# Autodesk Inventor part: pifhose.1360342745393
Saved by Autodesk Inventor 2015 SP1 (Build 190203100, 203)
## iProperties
IsCustomPart: 1
Company: Parker Hannifin
Created: 2013-02
Material: Rubber
Description: Tömlő
Document SubType Name: Modeling
Standard: Parker
Designer: Marci
Manufacturer: Parker
Language: hu-HU
Size Designation: 1/4 - 5
Categories: <MemberInstance><Categories><Category DisplayName="Csővezetékek" InternalName="4347fa0f-2144-441d-94cd-e3e15c92b736" Mnemonic="TUBEANDPIPE"><CategoryParameter D
Stock Number: Parker hidraulikatömlő - No Skive 1/4
Density: 1 g/cm^3
Appearance: Rubber - Black - Version 1.1
NAME: PIPING: Parker Hydraulic Hose - No Skive
DATA: <meta><inlinegroups number="1" deflen="12.7"></inlinegroups><connections number="2"></connections><angles><a>3.14159265358979</a></angles></meta>
L: 7,472 in
PL: 7,472 in
RPL: 7,500 in
OPL: 7,472 in
ROPL: 7,500 in
Author: Marci
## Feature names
1. Sweep1
## Parameters: ID = 6.35 mm, OD = 14.986 mm, L = 189.7888 mm, PL = 189.7888 mm, Size_Designation = 2.5 mm, d6 = 0, RPL = 190.5 mm, OPL = 189.7888 mm, ROPL = 190.5 mm, d7 = 0
